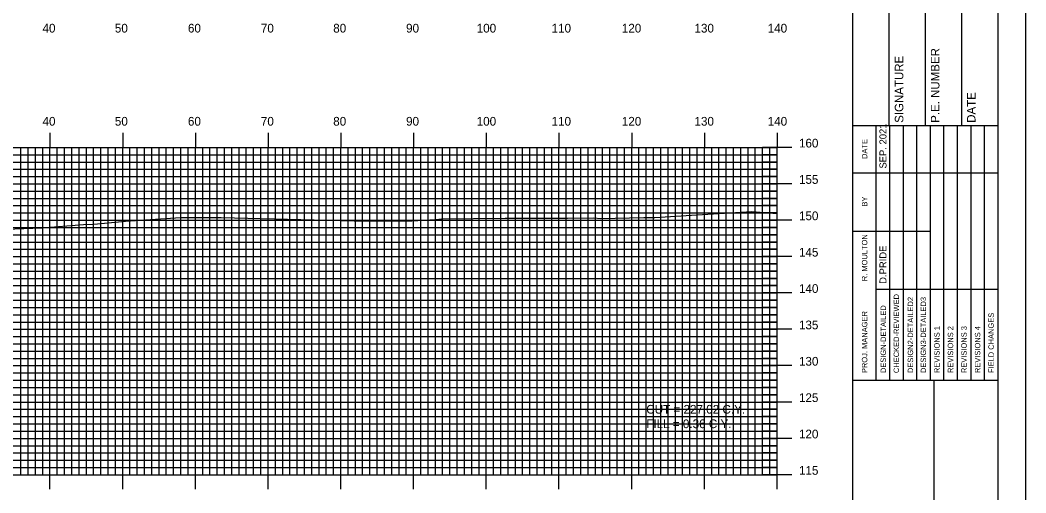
# Model space of a CAD drawing. Extents: x 861045 to 861388, y 364765 to 364985.
# Drawn here: x 861246.8 to 861385.1, y 364845.8 to 364910.8 of the extents above; entities that cross this region are included whole.
import ezdxf

# ---------------------------------------------------------------- set-up
doc = ezdxf.new("R2010")
doc.units = 0
for name, color, linetype in [('BORDER', 7, 'Continuous'), ('D_Text_Standard', 7, 'Continuous'), ('H_V ANNOTATION', 7, 'Continuous'), ('MAJOR', 7, 'Continuous'), ('MINOR', 7, 'Continuous'), ('PLOT BOUNDARY', 7, 'Continuous'), ('S_Roadway_Centerline', 7, 'Continuous')]:
    doc.layers.add(name, color=color, linetype=linetype)

msp = doc.modelspace()

# ---------------------------------------------------------------- linework, layer by layer
at = {"layer": 'BORDER'}
for p, q in [((861361.33, 364771.3), (861361.33, 364981.3)), ((861366.33, 364896.31), (861366.33, 364913.6)), ((861371.33, 364896.31), (861371.33, 364913.6)), ((861376.33, 364896.31), (861376.33, 364913.6)), ((861361.33, 364896.31), (861381.33, 364896.31)), ((861361.33, 364861.31), (861381.33, 364861.31)), ((861372.51, 364791.31), (861372.51, 364861.31))]:
    msp.add_line(p, q, dxfattribs=at)
msp.add_lwpolyline([(861061.33, 364771.3), (861381.33, 364771.3), (861381.33, 364981.3), (861061.33, 364981.3)], close=True, dxfattribs=at)
for points in [[(861364.56, 364889.81), (861364.56, 364896.31)], [(861366.42, 364861.31), (861366.42, 364896.31)], [(861368.28, 364896.31), (861368.28, 364861.31)], [(861370.15, 364861.31), (861370.15, 364896.31)], [(861372.01, 364861.31), (861372.01, 364896.31)], [(861373.87, 364861.31), (861373.87, 364896.31)], [(861375.74, 364861.31), (861375.74, 364896.31)], [(861377.6, 364861.31), (861377.6, 364896.31)], [(861379.46, 364861.31), (861379.46, 364896.31)], [(861364.56, 364861.31), (861364.56, 364894.9)], [(861361.33, 364889.81), (861381.33, 364889.81)], [(861361.33, 364881.81), (861364.56, 364881.81)], [(861364.56, 364881.81), (861372.01, 364881.81)], [(861364.56, 364873.81), (861381.33, 364873.81)]]:
    msp.add_lwpolyline(points, dxfattribs=at)
at = {"layer": 'MAJOR'}
for p, q in [((861250.93, 364895.31), (861250.93, 364893.3)), ((861260.93, 364895.31), (861260.93, 364893.3)), ((861270.93, 364895.31), (861270.93, 364893.3)), ((861280.93, 364895.31), (861280.93, 364893.3)), ((861290.93, 364895.31), (861290.93, 364893.3)), ((861300.93, 364895.31), (861300.93, 364893.3)), ((861310.93, 364895.31), (861310.93, 364893.3)), ((861320.93, 364895.31), (861320.93, 364893.3)), ((861330.93, 364895.31), (861330.93, 364893.3)), ((861340.93, 364895.31), (861340.93, 364893.3)), ((861350.93, 364895.31), (861350.93, 364893.3)), ((861070.93, 364893.3), (861350.93, 364893.3)), ((861070.93, 364893.3), (861350.93, 364893.3)), ((861250.93, 364848.3), (861250.93, 364893.3)), ((861260.93, 364848.3), (861260.93, 364893.3)), ((861270.93, 364848.3), (861270.93, 364893.3)), ((861280.93, 364848.3), (861280.93, 364893.3)), ((861290.93, 364848.3), (861290.93, 364893.3)), ((861300.93, 364848.3), (861300.93, 364893.3)), ((861310.93, 364848.3), (861310.93, 364893.3)), ((861320.93, 364848.3), (861320.93, 364893.3)), ((861330.93, 364848.3), (861330.93, 364893.3)), ((861340.93, 364848.3), (861340.93, 364893.3)), ((861352.93, 364893.3), (861348.92, 364893.3)), ((861350.93, 364848.3), (861350.93, 364893.3)), ((861350.93, 364848.3), (861350.93, 364893.3)), ((861070.93, 364888.3), (861350.93, 364888.3)), ((861352.93, 364888.3), (861348.92, 364888.3)), ((861070.93, 364883.3), (861350.93, 364883.3)), ((861352.93, 364883.3), (861348.92, 364883.3)), ((861070.93, 364878.3), (861350.93, 364878.3)), ((861352.93, 364878.3), (861348.92, 364878.3)), ((861070.93, 364873.3), (861350.93, 364873.3)), ((861352.93, 364873.3), (861348.92, 364873.3)), ((861070.93, 364868.3), (861350.93, 364868.3)), ((861352.93, 364868.3), (861348.92, 364868.3)), ((861070.93, 364863.3), (861350.93, 364863.3)), ((861352.93, 364863.3), (861348.92, 364863.3)), ((861070.93, 364858.3), (861350.93, 364858.3)), ((861352.93, 364858.3), (861348.92, 364858.3)), ((861070.93, 364853.3), (861350.93, 364853.3)), ((861352.93, 364853.3), (861348.92, 364853.3)), ((861070.93, 364848.3), (861350.93, 364848.3)), ((861070.93, 364848.3), (861350.93, 364848.3)), ((861250.93, 364846.3), (861250.93, 364848.3)), ((861260.93, 364846.3), (861260.93, 364848.3)), ((861270.93, 364846.3), (861270.93, 364848.3)), ((861280.93, 364846.3), (861280.93, 364848.3)), ((861290.93, 364846.3), (861290.93, 364848.3)), ((861300.93, 364846.3), (861300.93, 364848.3)), ((861310.93, 364846.3), (861310.93, 364848.3)), ((861320.93, 364846.3), (861320.93, 364848.3)), ((861330.93, 364846.3), (861330.93, 364848.3)), ((861340.93, 364846.3), (861340.93, 364848.3)), ((861352.93, 364848.3), (861348.92, 364848.3)), ((861350.93, 364846.3), (861350.93, 364848.3))]:
    msp.add_line(p, q, dxfattribs=at)
at = {"layer": 'MINOR'}
for p, q in [((861070.93, 364892.3), (861350.93, 364892.3)), ((861246.93, 364848.3), (861246.93, 364893.3)), ((861247.93, 364848.3), (861247.93, 364893.3)), ((861248.93, 364848.3), (861248.93, 364893.3)), ((861249.93, 364848.3), (861249.93, 364893.3)), ((861251.93, 364848.3), (861251.93, 364893.3)), ((861252.93, 364848.3), (861252.93, 364893.3)), ((861253.93, 364848.3), (861253.93, 364893.3)), ((861254.93, 364848.3), (861254.93, 364893.3)), ((861255.93, 364848.3), (861255.93, 364893.3)), ((861256.93, 364848.3), (861256.93, 364893.3)), ((861257.93, 364848.3), (861257.93, 364893.3)), ((861258.93, 364848.3), (861258.93, 364893.3)), ((861259.93, 364848.3), (861259.93, 364893.3)), ((861261.93, 364848.3), (861261.93, 364893.3)), ((861262.93, 364848.3), (861262.93, 364893.3)), ((861263.93, 364848.3), (861263.93, 364893.3)), ((861264.93, 364848.3), (861264.93, 364893.3)), ((861265.93, 364848.3), (861265.93, 364893.3)), ((861266.93, 364848.3), (861266.93, 364893.3)), ((861267.93, 364848.3), (861267.93, 364893.3)), ((861268.93, 364848.3), (861268.93, 364893.3)), ((861269.93, 364848.3), (861269.93, 364893.3)), ((861271.93, 364848.3), (861271.93, 364893.3)), ((861272.93, 364848.3), (861272.93, 364893.3)), ((861273.93, 364848.3), (861273.93, 364893.3)), ((861274.93, 364848.3), (861274.93, 364893.3)), ((861275.93, 364848.3), (861275.93, 364893.3)), ((861276.93, 364848.3), (861276.93, 364893.3)), ((861277.93, 364848.3), (861277.93, 364893.3)), ((861278.93, 364848.3), (861278.93, 364893.3)), ((861279.93, 364848.3), (861279.93, 364893.3)), ((861281.93, 364848.3), (861281.93, 364893.3)), ((861282.93, 364848.3), (861282.93, 364893.3)), ((861283.93, 364848.3), (861283.93, 364893.3)), ((861284.93, 364848.3), (861284.93, 364893.3)), ((861285.93, 364848.3), (861285.93, 364893.3)), ((861286.93, 364848.3), (861286.93, 364893.3)), ((861287.93, 364848.3), (861287.93, 364893.3)), ((861288.93, 364848.3), (861288.93, 364893.3)), ((861289.93, 364848.3), (861289.93, 364893.3)), ((861291.93, 364848.3), (861291.93, 364893.3)), ((861292.93, 364848.3), (861292.93, 364893.3)), ((861293.93, 364848.3), (861293.93, 364893.3)), ((861294.93, 364848.3), (861294.93, 364893.3)), ((861295.93, 364848.3), (861295.93, 364893.3)), ((861296.93, 364848.3), (861296.93, 364893.3)), ((861297.93, 364848.3), (861297.93, 364893.3)), ((861298.93, 364848.3), (861298.93, 364893.3)), ((861299.93, 364848.3), (861299.93, 364893.3)), ((861301.93, 364848.3), (861301.93, 364893.3)), ((861302.93, 364848.3), (861302.93, 364893.3)), ((861303.93, 364848.3), (861303.93, 364893.3)), ((861304.93, 364848.3), (861304.93, 364893.3)), ((861305.93, 364848.3), (861305.93, 364893.3)), ((861306.93, 364848.3), (861306.93, 364893.3)), ((861307.93, 364848.3), (861307.93, 364893.3)), ((861308.93, 364848.3), (861308.93, 364893.3)), ((861309.93, 364848.3), (861309.93, 364893.3)), ((861311.93, 364848.3), (861311.93, 364893.3)), ((861312.93, 364848.3), (861312.93, 364893.3)), ((861313.93, 364848.3), (861313.93, 364893.3)), ((861314.93, 364848.3), (861314.93, 364893.3)), ((861315.93, 364848.3), (861315.93, 364893.3)), ((861316.93, 364848.3), (861316.93, 364893.3)), ((861317.93, 364848.3), (861317.93, 364893.3)), ((861318.93, 364848.3), (861318.93, 364893.3)), ((861319.93, 364848.3), (861319.93, 364893.3)), ((861321.93, 364848.3), (861321.93, 364893.3)), ((861322.93, 364848.3), (861322.93, 364893.3)), ((861323.93, 364848.3), (861323.93, 364893.3)), ((861324.93, 364848.3), (861324.93, 364893.3)), ((861325.93, 364848.3), (861325.93, 364893.3)), ((861326.93, 364848.3), (861326.93, 364893.3)), ((861327.93, 364848.3), (861327.93, 364893.3)), ((861328.93, 364848.3), (861328.93, 364893.3)), ((861329.93, 364848.3), (861329.93, 364893.3)), ((861331.93, 364848.3), (861331.93, 364893.3)), ((861332.93, 364848.3), (861332.93, 364893.3)), ((861333.93, 364848.3), (861333.93, 364893.3)), ((861334.93, 364848.3), (861334.93, 364893.3)), ((861335.93, 364848.3), (861335.93, 364893.3)), ((861336.93, 364848.3), (861336.93, 364893.3)), ((861337.93, 364848.3), (861337.93, 364893.3)), ((861338.93, 364848.3), (861338.93, 364893.3)), ((861339.93, 364848.3), (861339.93, 364893.3)), ((861341.93, 364848.3), (861341.93, 364893.3)), ((861342.93, 364848.3), (861342.93, 364893.3)), ((861343.93, 364848.3), (861343.93, 364893.3)), ((861344.93, 364848.3), (861344.93, 364893.3)), ((861345.93, 364848.3), (861345.93, 364893.3)), ((861346.93, 364848.3), (861346.93, 364893.3)), ((861347.93, 364848.3), (861347.93, 364893.3)), ((861350.93, 364892.3), (861348.92, 364892.3)), ((861348.93, 364848.3), (861348.93, 364893.3)), ((861349.93, 364848.3), (861349.93, 364893.3)), ((861070.93, 364891.3), (861350.93, 364891.3)), ((861350.93, 364891.3), (861348.92, 364891.3)), ((861070.93, 364890.3), (861350.93, 364890.3)), ((861070.93, 364889.3), (861350.93, 364889.3)), ((861350.93, 364890.3), (861348.92, 364890.3)), ((861350.93, 364889.3), (861348.92, 364889.3)), ((861070.93, 364887.3), (861350.93, 364887.3)), ((861350.93, 364887.3), (861348.92, 364887.3)), ((861070.93, 364886.3), (861350.93, 364886.3)), ((861070.93, 364885.3), (861350.93, 364885.3)), ((861350.93, 364886.3), (861348.92, 364886.3)), ((861350.93, 364885.3), (861348.92, 364885.3)), ((861070.93, 364884.3), (861350.93, 364884.3)), ((861350.93, 364884.3), (861348.92, 364884.3)), ((861070.93, 364882.3), (861350.93, 364882.3)), ((861350.93, 364882.3), (861348.92, 364882.3)), ((861070.93, 364881.3), (861350.93, 364881.3)), ((861350.93, 364881.3), (861348.92, 364881.3)), ((861070.93, 364880.3), (861350.93, 364880.3)), ((861350.93, 364880.3), (861348.92, 364880.3)), ((861070.93, 364879.3), (861350.93, 364879.3)), ((861350.93, 364879.3), (861348.92, 364879.3)), ((861070.93, 364877.3), (861350.93, 364877.3)), ((861350.93, 364877.3), (861348.92, 364877.3)), ((861070.93, 364876.3), (861350.93, 364876.3)), ((861350.93, 364876.3), (861348.92, 364876.3)), ((861070.93, 364875.3), (861350.93, 364875.3)), ((861070.93, 364874.3), (861350.93, 364874.3)), ((861350.93, 364875.3), (861348.92, 364875.3)), ((861350.93, 364874.3), (861348.92, 364874.3)), ((861070.93, 364872.3), (861350.93, 364872.3)), ((861070.93, 364871.3), (861350.93, 364871.3)), ((861350.93, 364872.3), (861348.92, 364872.3)), ((861350.93, 364871.3), (861348.92, 364871.3)), ((861070.93, 364870.3), (861350.93, 364870.3)), ((861350.93, 364870.3), (861348.92, 364870.3)), ((861070.93, 364869.3), (861350.93, 364869.3)), ((861350.93, 364869.3), (861348.92, 364869.3)), ((861070.93, 364867.3), (861350.93, 364867.3)), ((861350.93, 364867.3), (861348.92, 364867.3)), ((861070.93, 364866.3), (861350.93, 364866.3)), ((861350.93, 364866.3), (861348.92, 364866.3)), ((861070.93, 364865.3), (861350.93, 364865.3)), ((861070.93, 364864.3), (861350.93, 364864.3)), ((861350.93, 364865.3), (861348.92, 364865.3)), ((861350.93, 364864.3), (861348.92, 364864.3)), ((861070.93, 364862.3), (861350.93, 364862.3)), ((861350.93, 364862.3), (861348.92, 364862.3)), ((861070.93, 364861.3), (861350.93, 364861.3)), ((861070.93, 364860.3), (861350.93, 364860.3)), ((861350.93, 364861.3), (861348.92, 364861.3)), ((861350.93, 364860.3), (861348.92, 364860.3)), ((861070.93, 364859.3), (861350.93, 364859.3)), ((861350.93, 364859.3), (861348.92, 364859.3)), ((861070.93, 364857.3), (861350.93, 364857.3)), ((861070.93, 364856.3), (861350.93, 364856.3)), ((861350.93, 364857.3), (861348.92, 364857.3)), ((861350.93, 364856.3), (861348.92, 364856.3)), ((861070.93, 364855.3), (861350.93, 364855.3)), ((861350.93, 364855.3), (861348.92, 364855.3)), ((861070.93, 364854.3), (861350.93, 364854.3)), ((861350.93, 364854.3), (861348.92, 364854.3)), ((861070.93, 364852.3), (861350.93, 364852.3)), ((861350.93, 364852.3), (861348.92, 364852.3)), ((861070.93, 364851.3), (861350.93, 364851.3)), ((861350.93, 364851.3), (861348.92, 364851.3)), ((861070.93, 364850.3), (861350.93, 364850.3)), ((861070.93, 364849.3), (861350.93, 364849.3)), ((861350.93, 364850.3), (861348.92, 364850.3)), ((861350.93, 364849.3), (861348.92, 364849.3))]:
    msp.add_line(p, q, dxfattribs=at)
at = {"layer": 'PLOT BOUNDARY'}
msp.add_lwpolyline([(861045.14, 364765.18), (861385.14, 364765.18), (861385.14, 364985.18), (861045.14, 364985.18)], close=True, dxfattribs=at)
at = {"layer": 'S_Roadway_Centerline'}
msp.add_lwpolyline([(861244.85, 364882.06), (861249.82, 364882.25), (861255.53, 364882.69), (861256.97, 364882.77), (861261.33, 364883.16), (861268.86, 364883.66), (861274.48, 364883.65), (861292.78, 364883.22), (861294.5, 364883.21), (861300.68, 364883.23), (861304, 364883.4), (861304.75, 364883.48), (861313.51, 364883.6), (861322.09, 364883.59), (861325.74, 364883.61), (861326.7, 364883.53), (861332.58, 364883.67), (861334.12, 364883.69), (861339.16, 364883.97), (861347.44, 364884.48), (861350.93, 364884.21)], dxfattribs=at)

# ---------------------------------------------------------------- texts
at = {"layer": 'BORDER'}
for s, height, p in [('SIGNATURE', 1.181, (861368.29, 364896.69)), ('P.E. NUMBER', 1.1811, (861373.25, 364896.69)), ('DATE', 1.181, (861378.21, 364896.69)), ('SEP. 2021', 0.969, (861365.97, 364890.4)), ('DATE', 0.743, (861363.33, 364891.72)), ('BY', 0.743, (861363.33, 364885.18)), ('R. MOULTON', 0.745, (861363.33, 364874.91)), ('D.PRIDE', 0.969, (861365.97, 364874.55)), ('CHECKED-REVIEWED', 0.7455, (861367.69, 364862.28)), ('DESIGN-DETAILED', 0.7455, (861365.9, 364862.28)), ('DESIGN2-DETAILED2', 0.7455, (861369.63, 364862.28)), ('DESIGN3-DETAILED3', 0.7455, (861371.41, 364862.28)), ('PROJ. MANAGER', 0.7455, (861363.33, 364862.28)), ('FIELD CHANGES', 0.7455, (861380.73, 364862.28)), ('REVISIONS 1', 0.7455, (861373.28, 364862.28)), ('REVISIONS 2', 0.7455, (861375.14, 364862.28)), ('REVISIONS 3', 0.7455, (861377, 364862.28)), ('REVISIONS 4', 0.7455, (861378.87, 364862.28))]:
    msp.add_text(s, height=height, rotation=90, dxfattribs=at).set_placement(p)
at = {"layer": 'D_Text_Standard'}
for s, p in [('CUT = 227.02 C.Y.', (861332.93, 364856.7)), ('FILL = 0.36 C.Y.', (861332.93, 364854.71))]:
    msp.add_text(s, height=1.2, dxfattribs=at).set_placement(p)
at = {"layer": 'H_V ANNOTATION'}
for s, p in [('40', (861249.9, 364909.1)), ('50', (861259.85, 364909.1)), ('60', (861269.9, 364909.1)), ('70', (861279.93, 364909.1)), ('80', (861289.88, 364909.1)), ('90', (861299.9, 364909.1)), ('100', (861309.61, 364909.1)), ('110', (861319.91, 364909.1)), ('120', (861329.57, 364909.1)), ('130', (861339.56, 364909.1)), ('140', (861349.63, 364909.1)), ('40', (861249.9, 364896.3)), ('50', (861259.85, 364896.3)), ('60', (861269.9, 364896.3)), ('70', (861279.93, 364896.3)), ('80', (861289.88, 364896.3)), ('90', (861299.9, 364896.3)), ('100', (861309.61, 364896.3)), ('110', (861319.91, 364896.3)), ('120', (861329.57, 364896.3)), ('130', (861339.56, 364896.3)), ('140', (861349.63, 364896.3)), ('160', (861353.93, 364893.3)), ('155', (861353.93, 364888.3)), ('150', (861353.93, 364883.3)), ('145', (861353.93, 364878.3)), ('140', (861353.93, 364873.3)), ('135', (861353.93, 364868.3)), ('130', (861353.93, 364863.3)), ('125', (861353.93, 364858.3)), ('120', (861353.93, 364853.3)), ('115', (861353.93, 364848.3))]:
    msp.add_text(s, height=1.2, dxfattribs=at).set_placement(p)

doc.saveas('drawing.dxf')
